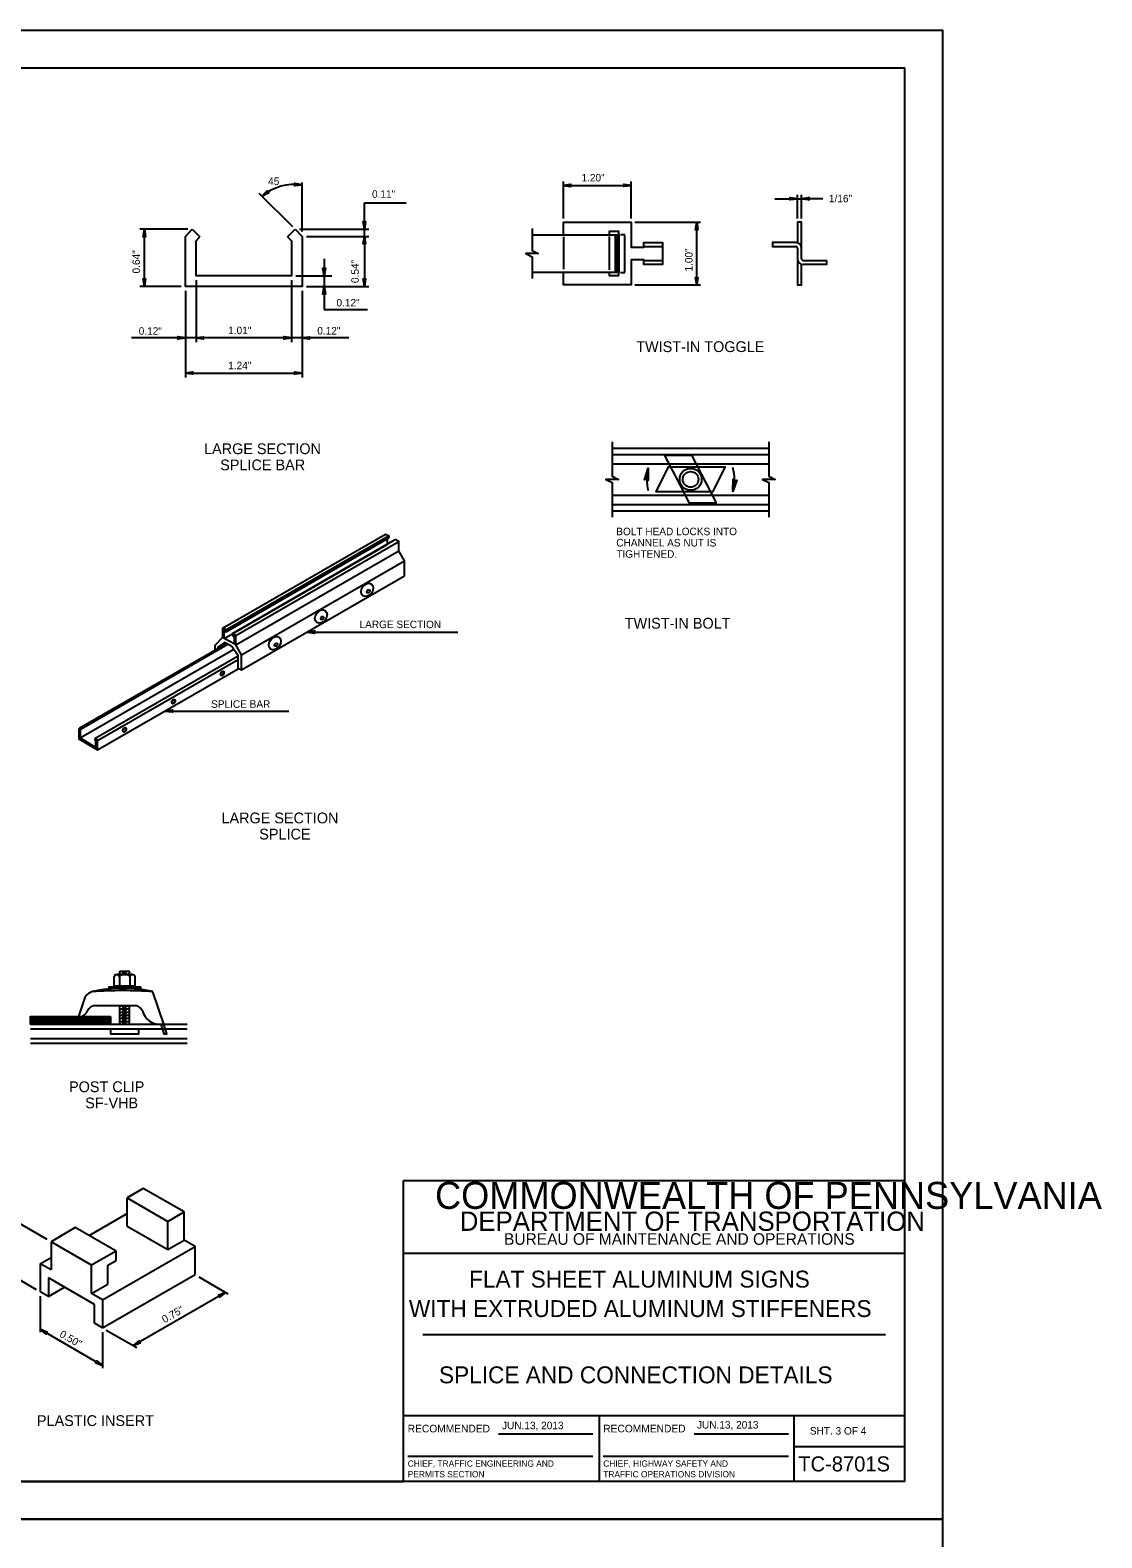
# Model space of a CAD drawing. Extents: x 650495 to 652241, y 298458 to 299646.
# Drawn here: x 651813 to 652241, y 299044 to 299646 of the extents above; entities that cross this region are included whole.
import ezdxf

# ---------------------------------------------------------------- set-up
doc = ezdxf.new("R2010")
doc.units = 0
for name, color, linetype in [('1', 7, 'Continuous'), ('2', 7, 'Continuous'), ('3', 7, 'Continuous'), ('PLT-BNDY', 7, 'Continuous')]:
    doc.layers.add(name, color=color, linetype=linetype)

# ---------------------------------------------------------------- blocks, each defined once
blk = doc.blocks.new('RARROW')
at = {"layer": '3'}
blk.add_lwpolyline([(-2.2695, 0.285), (-2.184875, 0.12075), (0, 0), (-2.2695, 0.285), (-2.38575, 0.384625), (0, 0), (-2.183125, -0.108), (-2.262875, -0.2705), (0, 0), (-2.38575, -0.379125), (-2.262875, -0.2705)], dxfattribs=at)

msp = doc.modelspace()

# ---------------------------------------------------------------- linework, layer by layer
at = {"layer": '1'}
for p, q in [((651376.31, 299630.63), (652162.31, 299630.63)), ((652162.31, 299066.63), (652162.31, 299630.63)), ((651962.31, 299066.63), (651962.31, 299186.63)), ((651962.31, 299186.63), (652162.31, 299186.63)), ((652162.31, 299157.63), (651962.31, 299157.63)), ((651970.06, 299125.31), (652154.56, 299125.31)), ((651962.31, 299093), (652162.31, 299093)), ((652040.31, 299093), (652040.31, 299066.63)), ((652118.19, 299066.63), (652118.19, 299093)), ((652000.24, 299085.57), (652037.87, 299085.57)), ((652078.24, 299085.57), (652115.87, 299085.57)), ((652118.19, 299080.63), (652162.31, 299080.63)), ((651963.99, 299076.68), (652037.87, 299076.68)), ((652041.99, 299076.68), (652115.87, 299076.68)), ((652162.31, 299066.63), (651376.31, 299066.63)), ((651376.31, 299066.63), (651962.31, 299066.63))]:
    msp.add_line(p, q, dxfattribs=at)
at = {"layer": '2'}
for p, q in [((651921.83, 299565.36), (651921.83, 299584.86)), ((652026.07, 299570.5), (652026.07, 299585.19)), ((652026.07, 299583.69), (652053.14, 299583.69)), ((652053.14, 299570.5), (652053.14, 299585.19)), ((651918.21, 299567.11), (651904.71, 299580.49)), ((652110.44, 299578.38), (652121.06, 299578.38)), ((652119.44, 299570.5), (652119.44, 299579.88)), ((652121.06, 299570.5), (652121.06, 299579.88)), ((652129.62, 299578.38), (652121.06, 299578.38)), ((651946.71, 299563.36), (651946.71, 299576.74)), ((651946.71, 299576.74), (651963.43, 299576.74)), ((651876.33, 299566.23), (651857.21, 299566.23)), ((651858.96, 299543.36), (651858.96, 299566.23)), ((651878.08, 299566.23), (651881.08, 299563.11)), ((651916.08, 299563.11), (651919.08, 299566.23)), ((651920.83, 299566.23), (651948.46, 299566.23)), ((652054.64, 299569), (652080.76, 299569)), ((652079.26, 299544), (652079.26, 299569)), ((651923.58, 299563.36), (651948.46, 299563.36)), ((651946.71, 299563.36), (651946.71, 299543.36)), ((652026.07, 299563.11), (652026.07, 299550.32)), ((652044.39, 299563.28), (652044.39, 299550.04)), ((652046.76, 299564), (652046.76, 299549)), ((652047.51, 299564), (652047.51, 299549)), ((652050.64, 299564), (652048.82, 299564)), ((652050.64, 299549), (652050.64, 299564)), ((652058.14, 299559.38), (652065.64, 299559.38)), ((651930.65, 299554.37), (651930.65, 299547.61)), ((652058.49, 299553.75), (652065.64, 299553.75)), ((652119.44, 299558.63), (652119.44, 299554.5)), ((651919.33, 299547.61), (651933.72, 299547.61)), ((651930.65, 299547.61), (651930.65, 299534.23)), ((652048.93, 299549), (652050.64, 299549)), ((651873.58, 299543.36), (651857.21, 299543.36)), ((651875.33, 299541.61), (651875.33, 299507.08)), ((651879.58, 299545.86), (651879.58, 299521.09)), ((651917.58, 299545.86), (651917.58, 299521.09)), ((651921.83, 299541.61), (651921.83, 299507.08)), ((651923.58, 299543.36), (651948.46, 299543.36)), ((652054.64, 299544), (652080.76, 299544)), ((651930.65, 299534.23), (651947.91, 299534.23)), ((651879.58, 299522.84), (651853.83, 299522.84)), ((651917.58, 299522.84), (651879.58, 299522.84)), ((651940.46, 299522.84), (651917.58, 299522.84)), ((651875.33, 299508.83), (651921.83, 299508.83)), ((652045.56, 299478.88), (652108.06, 299478.88)), ((652045.56, 299476.38), (652108.06, 299476.38)), ((652045.56, 299472.63), (652108.06, 299472.63)), ((652045.56, 299460.13), (652108.06, 299460.13)), ((652045.56, 299456.38), (652108.06, 299456.38)), ((652045.56, 299453.88), (652108.06, 299453.88)), ((651890.15, 299407.11), (651955.15, 299444.61)), ((651890.78, 299405.99), (651955.78, 299443.49)), ((651890.78, 299402.99), (651955.78, 299440.49)), ((651891.53, 299406.36), (651956.4, 299443.86)), ((651891.53, 299405.61), (651956.4, 299443.11)), ((651894.15, 299404.86), (651959.03, 299442.36)), ((651895.4, 299404.11), (651960.4, 299441.61)), ((651895.4, 299400.36), (651960.4, 299437.86)), ((651897.65, 299396.36), (651962.65, 299433.86)), ((651897.65, 299390.36), (651962.65, 299427.86)), ((651923.9, 299405.49), (651983.95, 299405.49)), ((651833.4, 299363.24), (651894.65, 299398.61)), ((651833.65, 299367.49), (651891.65, 299400.99)), ((651834.03, 299366.99), (651892.28, 299400.61)), ((651839.65, 299363.24), (651896.4, 299395.99)), ((651840.28, 299362.24), (651896.4, 299394.61)), ((651840.28, 299358.49), (651896.4, 299390.86)), ((651867.15, 299373.99), (651916.57, 299373.99)), ((651834.03, 299366.99), (651833.65, 299367.49)), ((651839.65, 299363.24), (651839.15, 299362.99)), ((651846.85, 299264.39), (651846.85, 299268.14)), ((651846.85, 299264.39), (651855.22, 299264.39)), ((651847.22, 299264.39), (651847.22, 299264.14)), ((651854.1, 299268.89), (651847.97, 299268.89)), ((651848.97, 299268.02), (651848.97, 299264.39)), ((651849.22, 299270.27), (651852.97, 299270.27)), ((651849.22, 299268.89), (651849.22, 299270.27)), ((651849.35, 299270.14), (651852.72, 299270.14)), ((651850.1, 299269.52), (651851.85, 299269.52)), ((651852.97, 299268.89), (651852.97, 299270.27)), ((651853.22, 299268.02), (651853.22, 299264.39)), ((651854.97, 299264.39), (651854.97, 299264.14)), ((651855.22, 299264.39), (651855.22, 299268.14)), ((651832.85, 299252.14), (651835.47, 299260.14)), ((651847.22, 299264.14), (651854.97, 299264.14)), ((651866.72, 299249.02), (651862.35, 299262.02)), ((651839.22, 299256.52), (651855.47, 299256.52)), ((651849.22, 299249.02), (651849.22, 299256.52)), ((651849.35, 299256.39), (651852.72, 299256.39)), ((651849.35, 299255.14), (651852.72, 299255.14)), ((651849.35, 299253.89), (651852.72, 299253.89)), ((651849.35, 299252.64), (651852.72, 299252.64)), ((651850.1, 299255.77), (651851.85, 299255.77)), ((651850.1, 299254.52), (651851.85, 299254.52)), ((651850.1, 299253.27), (651851.85, 299253.27)), ((651852.97, 299249.02), (651852.97, 299256.52)), ((651813.47, 299249.02), (651875.97, 299249.02)), ((651813.47, 299247.14), (651875.97, 299247.14)), ((651849.35, 299251.39), (651852.72, 299251.39)), ((651849.35, 299250.14), (651852.72, 299250.14)), ((651850.1, 299252.02), (651851.85, 299252.02)), ((651850.1, 299250.77), (651851.85, 299250.77)), ((651850.1, 299249.52), (651851.85, 299249.52)), ((651856.72, 299247.14), (651856.72, 299247.14)), ((651865.47, 299249.02), (651865.47, 299249.02)), ((651813.47, 299243.39), (651875.97, 299243.39)), ((651813.47, 299241.52), (651875.97, 299241.52)), ((651858.53, 299183.51), (651852.03, 299179.76)), ((651874.78, 299174.13), (651858.53, 299183.51)), ((651852.03, 299179.76), (651868.28, 299170.38)), ((651852.03, 299168.51), (651852.03, 299179.76)), ((651868.28, 299170.38), (651874.78, 299174.13)), ((651874.78, 299162.88), (651874.78, 299174.13)), ((651820.16, 299163.13), (651802.78, 299173.28)), ((651836.91, 299164.76), (651852.03, 299173.51)), ((651852.03, 299168.51), (651868.28, 299159.13)), ((651868.28, 299159.13), (651868.28, 299170.38)), ((651831.41, 299167.88), (651821.78, 299162.26)), ((651837.91, 299152.88), (651821.78, 299162.26)), ((651821.78, 299162.26), (651821.78, 299151.01)), ((651847.66, 299158.51), (651831.41, 299167.88)), ((651868.28, 299159.13), (651874.78, 299162.88)), ((651879.16, 299160.38), (651874.78, 299162.88)), ((651847.66, 299158.51), (651837.91, 299152.88)), ((651842.28, 299139.13), (651879.16, 299160.38)), ((651847.66, 299154.76), (651847.66, 299158.51)), ((651879.16, 299149.13), (651879.16, 299160.38)), ((651815.91, 299143.13), (651802.59, 299150.9)), ((651817.41, 299153.51), (651821.78, 299156.01)), ((651817.41, 299153.51), (651817.41, 299142.26)), ((651821.78, 299151.01), (651817.41, 299153.51)), ((651837.91, 299141.63), (651837.91, 299152.88)), ((651844.41, 299152.88), (651847.66, 299154.76)), ((651844.41, 299145.38), (651844.41, 299152.88)), ((651839.03, 299137.26), (651820.66, 299147.88)), ((651820.66, 299147.88), (651820.66, 299140.38)), ((651820.66, 299140.38), (651827.16, 299144.13)), ((651837.91, 299141.63), (651844.41, 299145.38)), ((651842.28, 299127.88), (651879.16, 299149.13)), ((651880.66, 299148.26), (651892.28, 299141.49)), ((651820.66, 299140.38), (651817.41, 299142.26)), ((651817.41, 299140.51), (651817.41, 299126.13)), ((651842.28, 299139.13), (651837.91, 299141.63)), ((651842.28, 299139.13), (651842.28, 299127.88)), ((651891.3, 299142.06), (651854.58, 299120.84)), ((651839.03, 299129.76), (651839.03, 299137.26)), ((651817.41, 299127.36), (651842.28, 299112.84)), ((651842.28, 299127.88), (651839.03, 299129.76)), ((651842.28, 299126.13), (651842.28, 299111.76)), ((651843.78, 299127.01), (651855.99, 299120.03))]:
    msp.add_line(p, q, dxfattribs=at)
for points in [[(651919.08, 299566.23), (651921.83, 299563.36), (651921.83, 299543.36), (651875.33, 299543.36), (651875.33, 299563.36), (651878.08, 299566.23)], [(652013.57, 299566.5), (652013.57, 299557.75), (652016.07, 299556.5), (652011.07, 299556.5), (652013.57, 299555.25), (652013.57, 299546.5)], [(652026.07, 299564), (652026.07, 299569), (652053.14, 299569), (652053.14, 299559), (652058.14, 299559), (652058.14, 299560.88), (652065.64, 299560.88), (652065.64, 299552.13), (652058.14, 299552.13), (652058.14, 299554), (652053.14, 299554), (652053.14, 299544), (652026.07, 299544), (652026.07, 299549)], [(652121.06, 299554.5), (652121.06, 299569), (652119.44, 299569), (652119.44, 299560.78)], [(651916.08, 299563.11), (651917.58, 299561.61), (651917.58, 299547.61), (651879.58, 299547.61), (651879.58, 299561.61), (651881.08, 299563.11)], [(652013.57, 299564), (652048.14, 299564), (652048.14, 299549), (652013.57, 299549)], [(652118.76, 299560.88), (652109.44, 299560.88), (652109.44, 299559.38), (652118.69, 299559.38)], [(652119.44, 299558.63), (652119.44, 299544), (652121.06, 299544), (652121.06, 299552.23)], [(652121.81, 299553.75), (652131.06, 299553.75), (652131.06, 299552.13), (652121.74, 299552.13)], [(652045.56, 299481.38), (652045.56, 299467.63), (652048.06, 299466.38), (652043.06, 299466.38), (652045.56, 299465.13), (652045.56, 299451.38)], [(652108.06, 299481.38), (652108.06, 299467.63), (652110.56, 299466.38), (652105.56, 299466.38), (652108.06, 299465.13), (652108.06, 299451.38)], [(652072.69, 299464.25), (652066.56, 299475.88), (652077.19, 299476), (652087.06, 299457), (652076.44, 299456.88), (652072.69, 299464.25)], [(652058.69, 299466.5), (652058.94, 299466.63), (652059.94, 299470.88), (652058.69, 299466.5), (652058.44, 299466.25), (652059.94, 299470.88), (652059.44, 299466.5), (652059.69, 299466.38), (652059.94, 299470.88), (652059.94, 299466), (652059.69, 299466.38)], [(652076.81, 299471.38), (652090.56, 299471.38), (652085.56, 299461.38), (652063.06, 299461.38), (652068.06, 299471.38), (652076.81, 299471.38)], [(652095.06, 299466), (652094.69, 299465.88), (652093.69, 299461.63), (652095.06, 299466), (652095.31, 299466.13), (652093.69, 299461.63), (652094.19, 299466), (652093.94, 299466.13), (652093.69, 299461.63), (652093.81, 299466.5), (652093.94, 299466.13)], [(651955.15, 299444.61), (651956.4, 299443.86), (651956.4, 299443.11)], [(651955.78, 299442.74), (651955.78, 299440.49)], [(651962.65, 299427.86), (651962.65, 299433.86), (651960.4, 299437.86), (651960.4, 299441.61), (651959.03, 299442.36)], [(651896.4, 299391.11), (651897.65, 299390.36), (651897.65, 299396.36), (651895.4, 299400.36), (651895.4, 299404.11), (651894.15, 299404.86), (651894.15, 299404.11), (651894.78, 299403.74), (651894.78, 299400.74), (651890.78, 299402.99), (651890.78, 299405.99), (651891.53, 299405.61), (651891.53, 299406.36), (651890.15, 299407.11), (651890.15, 299403.36), (651887.03, 299400.11), (651887.03, 299398.24)], [(651896.4, 299391.11), (651896.4, 299395.99), (651893.9, 299399.74), (651890.9, 299401.36), (651888.28, 299399.49), (651888.28, 299398.99)], [(651833.65, 299367.49), (651832.78, 299366.61), (651832.78, 299362.86), (651840.28, 299358.49), (651840.28, 299362.24), (651839.65, 299363.24)], [(651834.03, 299366.99), (651833.4, 299366.36), (651833.4, 299363.24), (651839.65, 299359.49), (651839.65, 299361.99), (651839.15, 299362.99)], [(651813.72, 299251.52), (651844.97, 299251.52), (651844.97, 299249.64), (651813.72, 299249.39), (651813.72, 299251.14), (651844.47, 299251.14), (651844.6, 299250.14), (651814.35, 299249.64), (651814.47, 299250.64), (651843.72, 299250.64), (651843.72, 299250.52), (651814.6, 299250.14)], [(651845.47, 299247.14), (651845.47, 299245.27), (651856.72, 299245.27), (651856.72, 299247.14)], [(651865.47, 299249.02), (651866.72, 299245.27), (651867.97, 299245.27), (651866.72, 299249.02)]]:
    msp.add_lwpolyline(points, dxfattribs=at)
for points in [[(652048.14, 299564), (652048.14, 299565.25), (652044.39, 299565.25), (652044.39, 299564)], [(652048.14, 299547.75), (652048.14, 299549), (652044.39, 299549), (652044.39, 299547.75)], [(651844.85, 299263.27), (651844.85, 299263.89), (651857.35, 299263.89), (651857.35, 299263.27)], [(651845.47, 299252.14), (651845.47, 299249.02), (651813.47, 299249.02), (651813.47, 299252.14)]]:
    msp.add_lwpolyline(points, close=True, dxfattribs=at)
for radius in [4.38, 3.12]:
    msp.add_circle((652076.85, 299466.42), radius, dxfattribs=at)
for centre, radius, start, end in [((651918.83, 299563.94), 20.14, 81.42065, 130.10106), ((652118.69, 299558.63), 0.75, 0, 90), ((652118.76, 299558.58), 2.3, 0, 90), ((652121.74, 299554.43), 2.3, 180, 270), ((652121.81, 299554.5), 0.75, 180, 270), ((652076.85, 299466.42), 17.49, 165.2574, 194.94011), ((652076.85, 299466.42), 17.49, 344.07384, 15.48813), ((651848.03, 299268.76), 0.113, 90, 180), ((651854.1, 299268.76), 0.113, 0, 90), ((651839.31, 299257.56), 4.6, 103.47229, 145.70272), ((651850.31, 299206.21), 57.12, 77.80349, 102.1965), ((651850.31, 299087.5), 174.95, 86.04462, 93.95539), ((651832.89, 299255.49), 3.48, 282.55259, 342.47234), ((651839.61, 299252.69), 3.82, 95.78592, 152.80494), ((651854.51, 299252.45), 4.15, 26.88629, 76.60858), ((651865.12, 299256.12), 7.13, 194.52183, 272.8108)]:
    msp.add_arc(centre, radius, start, end, dxfattribs=at)
for centre, major_axis, ratio in [((651947.81, 299422.32), (1.7, 2.34), 0.738176), ((651948.29, 299421.73), (0.425, 0.585), 0.738176), ((651929.41, 299411.69), (1.7, 2.34), 0.738176), ((651929.89, 299411.11), (0.425, 0.585), 0.738176), ((651911, 299401.07), (1.7, 2.34), 0.738176), ((651911.48, 299400.48), (0.425, 0.585), 0.738176), ((651890.05, 299389.01), (0.443, 0.822), 0.636755), ((651870.56, 299377.76), (0.443, 0.822), 0.636755), ((651851.07, 299366.51), (0.443, 0.822), 0.636755)]:
    msp.add_ellipse(centre, major_axis=major_axis, ratio=ratio, dxfattribs=at)
for centre, major_axis, ratio, start_param, end_param in [((651889.88, 299389.1), (0.443, 0.822), 0.636755, 3.280378, 6.105665), ((651870.4, 299377.85), (0.443, 0.822), 0.636755, 3.280378, 6.105665), ((651850.91, 299366.6), (0.443, 0.822), 0.636755, 3.280378, 6.105665), ((651847.91, 299268.04), (1.03, 0.01), 0.679853, 0, 3.035161), ((651851.06, 299268.06), (-2.12, -0.01), 0.335964, 3.141593, 6.283185), ((651854.21, 299268.06), (-1.03, 0.01), 0.679853, 3.248025, 6.283185)]:
    msp.add_ellipse(centre, major_axis=major_axis, ratio=ratio, start_param=start_param, end_param=end_param, dxfattribs=at)
at = {"layer": 'PLT-BNDY'}
for points in [[(651336.31, 299645.63), (652177.31, 299645.63), (652177.31, 299051.63), (651336.31, 299051.63)], [(651336.31, 299051.63), (652177.31, 299051.63), (652177.31, 298457.63), (651336.31, 298457.63)]]:
    msp.add_lwpolyline(points, close=True, dxfattribs=at)

# ---------------------------------------------------------------- block references
at = {"layer": '2'}
for p, xscale, yscale, rotation in [((651921.83, 299583.86), 1.257434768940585, 1.3092961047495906, -4.1307990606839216), ((652026.07, 299583.69), 1.2574347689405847, 1.3092961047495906, 180), ((651905.86, 299579.35), 1.2574347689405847, 1.3092961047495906, -143.18293648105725), ((652121.06, 299578.38), 1.2574347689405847, 1.3092961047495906, 180), ((651858.96, 299566.23), 1.2574347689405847, 1.3092961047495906, 89.99999999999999), ((651946.71, 299566.23), 1.2574347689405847, 1.3092961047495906, -90.00000000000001), ((652079.26, 299569), 1.2574347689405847, 1.3092961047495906, 89.99999999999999), ((651946.71, 299563.36), 1.2574347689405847, 1.3092961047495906, 89.99999999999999), ((651930.65, 299547.61), 1.2574347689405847, 1.3092961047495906, -90.00000000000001), ((652079.26, 299544), 1.2574347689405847, 1.3092961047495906, -90.00000000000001), ((651858.96, 299543.36), 1.2574347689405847, 1.3092961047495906, -90.00000000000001), ((651930.65, 299543.36), 1.2574347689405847, 1.3092961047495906, 89.99999999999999), ((651946.71, 299543.36), 1.2574347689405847, 1.3092961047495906, -90.00000000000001), ((651879.58, 299522.84), 1.2574347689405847, 1.3092961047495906, 180), ((651921.83, 299522.84), 1.2574347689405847, 1.3092961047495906, 180), ((651875.33, 299508.83), 1.2574347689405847, 1.3092961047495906, 180), ((651923.9, 299405.49), 1.2574347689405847, 1.3092961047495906, 180), ((651867.15, 299373.99), 1.2574347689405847, 1.3092961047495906, 180), ((651891.3, 299142.06), 1.2574347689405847, 1.3092961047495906, 30.434578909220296), ((651817.41, 299127.35), 1.2574347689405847, 1.3092961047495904, 149.64469446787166), ((651854.58, 299120.84), 1.2574347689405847, 1.3092961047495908, -149.86157797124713), ((651842.28, 299112.84), 1.2574347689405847, 1.3092961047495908, -30.0868603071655)]:
    msp.add_blockref('RARROW', p, dxfattribs=dict(at, xscale=xscale, yscale=yscale, rotation=rotation))
at = {"layer": '2', "xscale": 1.2574347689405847, "yscale": 1.3092961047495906}
for p in [(652053.14, 299583.69), (652119.44, 299578.38), (651875.33, 299522.84), (651917.58, 299522.84), (651921.83, 299508.83)]:
    msp.add_blockref('RARROW', p, dxfattribs=at)

# ---------------------------------------------------------------- texts
at = {"layer": '1'}
for s, height, p in [('COMMONWEALTH OF PENNSYLVANIA', 10.7828, (651974.9, 299175.36)), ('DEPARTMENT OF TRANSPORTATION', 7.6837, (651984.76, 299166.61)), ('BUREAU OF MAINTENANCE AND OPERATIONS', 4.6253, (652002.41, 299161.04)), ('FLAT SHEET ALUMINUM SIGNS', 6.75, (651988.47, 299143.97)), ('WITH EXTRUDED ALUMINUM STIFFENERS', 6.75, (651964.47, 299132.22)), ('SPLICE AND CONNECTION DETAILS', 6.75, (651976.47, 299105.78)), ('RECOMMENDED', 3.048, (651963.99, 299086.2)), ('RECOMMENDED', 3.048, (652041.99, 299086.2)), ('SHT. 3 OF 4', 3, (652124.4, 299085.31)), ('CHIEF, TRAFFIC ENGINEERING AND', 2.5, (651963.99, 299072.51)), ('CHIEF, HIGHWAY SAFETY AND', 2.5, (652041.99, 299072.51)), ('TC-8701S', 6, (652119.79, 299070.63)), ('PERMITS SECTION', 2.5, (651963.99, 299068.26)), ('TRAFFIC OPERATIONS DIVISION', 2.5, (652041.99, 299068.26))]:
    msp.add_text(s, height=height, dxfattribs=at).set_placement(p)
at = {"layer": '2'}
for s, height, p in [('45', 2.999, (651908.33, 299583.86)), ('1.20"', 3, (652033.31, 299585.25)), ('0.11"', 3, (651949.75, 299578.74)), ('1/16"', 3, (652132.02, 299576.95)), ('0.12"', 3, (651935.58, 299535.39)), ('0.12"', 3, (651856.7, 299524.1)), ('1.01"', 3, (651892.4, 299524.34)), ('0.12"', 3, (651927.92, 299524.2)), ('TWIST-IN TOGGLE', 4.3, (652055.15, 299517.2)), ('1.24"', 3, (651892.39, 299510.32)), ('LARGE SECTION', 4.3, (651882.76, 299476.48)), ('SPLICE BAR', 4.3, (651889.21, 299470.03)), ('BOLT HEAD LOCKS INTO', 3, (652047.19, 299444.13)), ('CHANNEL AS NUT IS', 3, (652047.19, 299439.63)), ('TIGHTENED.', 3, (652047.19, 299435.13)), ('LARGE SECTION', 3, (651944.77, 299407.05)), ('TWIST-IN BOLT', 4.3, (652050.57, 299406.86)), ('SPLICE BAR', 3, (651885.57, 299375.27)), ('LARGE SECTION', 4.3, (651889.71, 299329.18)), ('SPLICE', 4.3, (651904.78, 299322.73)), ('POST CLIP', 4.3, (651828.91, 299221.94)), ('SF-VHB', 4.3, (651835.36, 299215.49)), ('PLASTIC INSERT', 4.3, (651816.11, 299088.74)), ('JUN.13, 2013', 3, (652001.61, 299087.45)), ('JUN.13, 2013', 3, (652079.37, 299087.72))]:
    msp.add_text(s, height=height, dxfattribs=at).set_placement(p)
for s, rotation, p in [('0.64"', 90, (651857.21, 299548.57)), (' 0.54"', 90, (651944.47, 299543.63)), ('1.00"', 90, (652077.62, 299549.33)), ('0.75"', 30.02706, (651867.02, 299129.69)), ('0.50"', 329.74364, (651824.86, 299124.56))]:
    msp.add_text(s, height=3, rotation=rotation, dxfattribs=at).set_placement(p)

doc.saveas('drawing.dxf')
